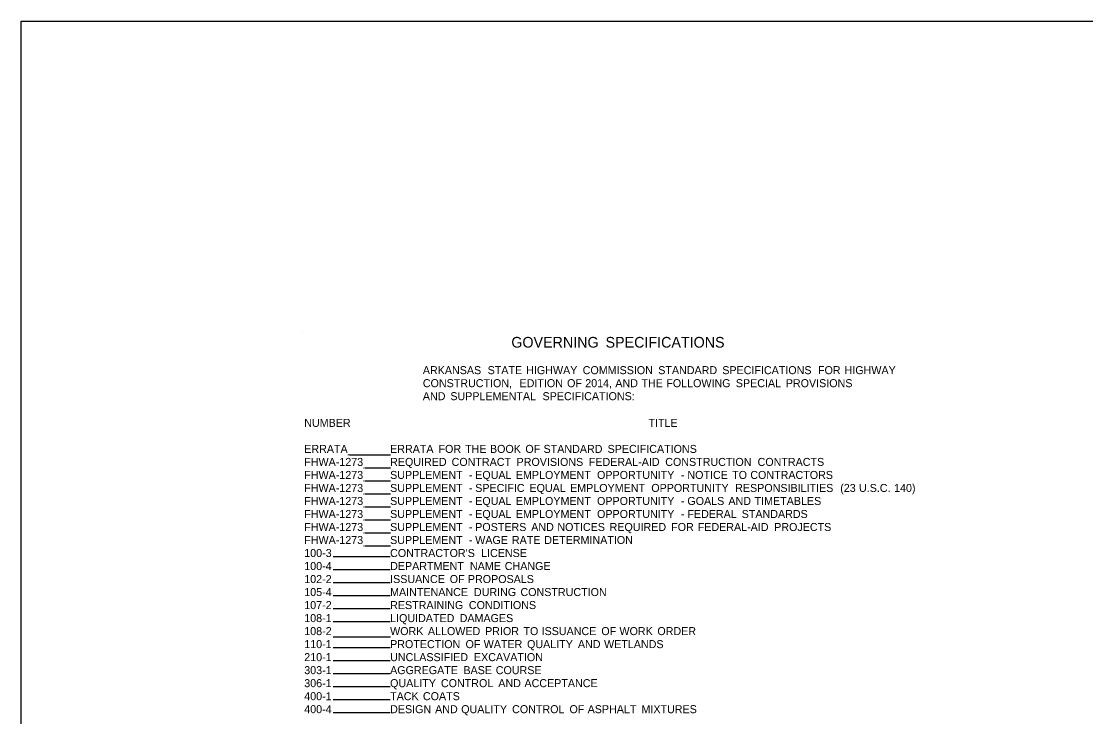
# Model space of a CAD drawing. Extents: x 1955683 to 1956002, y 566394 to 566602.
# Drawn here: x 1955683.4 to 1955842.9, y 566497.8 to 566602 of the extents above; entities that cross this region are included whole.
import ezdxf

# ---------------------------------------------------------------- set-up
doc = ezdxf.new("R2010")
doc.units = 0
for name, color, linetype in [('Default', 7, 'Continuous'), ('R_Border', 7, 'Continuous'), ('R_Border Prem', 7, 'Continuous')]:
    doc.layers.add(name, color=color, linetype=linetype)

msp = doc.modelspace()

# ---------------------------------------------------------------- linework, layer by layer
at = {"layer": 'R_Border'}
for p, q in [((1955725.6, 566555.39), (1955725.6, 566555.39)), ((1955732.57, 566537.03), (1955738.72, 566537.03)), ((1955734.9, 566535.08), (1955738.72, 566535.08)), ((1955734.9, 566533.13), (1955738.72, 566533.13)), ((1955734.9, 566531.18), (1955738.72, 566531.18)), ((1955734.9, 566529.23), (1955738.72, 566529.23)), ((1955734.9, 566527.28), (1955738.72, 566527.28)), ((1955734.9, 566525.33), (1955738.72, 566525.33)), ((1955734.9, 566523.38), (1955738.72, 566523.38)), ((1955730.1, 566521.79), (1955738.66, 566521.79)), ((1955730.1, 566519.84), (1955738.66, 566519.84)), ((1955730.1, 566517.89), (1955738.66, 566517.89)), ((1955730.1, 566515.94), (1955738.66, 566515.94)), ((1955730.1, 566513.99), (1955738.66, 566513.99)), ((1955730.1, 566512.04), (1955738.66, 566512.04)), ((1955730.1, 566509.73), (1955738.72, 566509.73)), ((1955730.1, 566508.14), (1955738.66, 566508.14)), ((1955730.1, 566506.19), (1955738.66, 566506.19)), ((1955730.1, 566504.24), (1955738.66, 566504.24)), ((1955730.1, 566502.29), (1955738.66, 566502.29)), ((1955730.1, 566500.34), (1955738.66, 566500.34)), ((1955730.1, 566498.39), (1955738.66, 566498.39))]:
    msp.add_line(p, q, dxfattribs=at)
at = {"layer": 'R_Border Prem'}
msp.add_lwpolyline([(1956002.45, 566561.79), (1956002.45, 566393.51), (1955683.38, 566393.51), (1955683.38, 566601.97), (1955920.19, 566601.97), (1955920.19, 566592.09), (1955955.71, 566592.09), (1955955.71, 566588.52), (1955959.35, 566588.52), (1955959.35, 566589.17), (1955974.89, 566589.17)], dxfattribs=at)

# ---------------------------------------------------------------- texts
at = {"layer": 'Default'}
for s, height, p in [('GOVERNING', 1.6, (1955756.83, 566553.08)), (' SPECIFICATIONS', 1.6, (1955770.36, 566553.08)), ('           ARKANSAS', 1.2, (1955738.66, 566549.1)), (' STATE', 1.2, (1955752.83, 566549.1)), (' HIGHWAY', 1.2, (1955758.61, 566549.1)), (' COMMISSION', 1.2, (1955767.08, 566549.1)), (' STANDARD', 1.2, (1955778.4, 566549.1)), (' SPECIFICATIONS', 1.2, (1955788, 566549.1)), (' FOR', 1.2, (1955802.35, 566549.1)), (' HIGHWAY', 1.2, (1955806.33, 566549.1)), ('           CONSTRUCTION,', 1.2, (1955738.66, 566547.15)), (' EDITION', 1.2, (1955757.61, 566547.15)), (' OF', 1.2, (1955764.74, 566547.15)), (' 2014,', 1.2, (1955767.46, 566547.15)), (' AND', 1.2, (1955771.97, 566547.15)), (' THE', 1.2, (1955775.88, 566547.15)), (' FOLLOWING', 1.2, (1955779.61, 566547.15)), (' SPECIAL', 1.2, (1955790.03, 566547.15)), (' PROVISIONS', 1.2, (1955797.52, 566547.15)), ('           AND', 1.2, (1955738.66, 566545.2)), (' SUPPLEMENTAL', 1.2, (1955747.24, 566545.2)), (' SPECIFICATIONS:', 1.2, (1955761.06, 566545.2)), ('NUMBER', 1.2, (1955725.79, 566541.2)), ('TITLE', 1.2, (1955777.38, 566541.2)), ('ERRATA______', 1.2, (1955725.79, 566537.3)), ('ERRATA', 1.2, (1955738.66, 566537.3)), (' FOR', 1.2, (1955745.47, 566537.3)), (' THE', 1.2, (1955749.45, 566537.3)), (' BOOK', 1.2, (1955753.18, 566537.3)), (' OF', 1.2, (1955758.49, 566537.3)), (' STANDARD', 1.2, (1955761.21, 566537.3)), (' SPECIFICATIONS', 1.2, (1955770.81, 566537.3)), ('FHWA-1273___', 1.2, (1955725.79, 566535.35)), ('REQUIRED', 1.2, (1955738.66, 566535.35)), (' CONTRACT', 1.2, (1955747.43, 566535.35)), (' PROVISIONS', 1.2, (1955757.17, 566535.35)), (' FEDERAL-AID', 1.2, (1955767.99, 566535.35)), (' CONSTRUCTION', 1.2, (1955779.45, 566535.35)), (' CONTRACTS', 1.2, (1955793.29, 566535.35)), ('FHWA-1273___', 1.2, (1955725.79, 566533.4)), ('SUPPLEMENT', 1.2, (1955738.66, 566533.4)), (' -', 1.2, (1955750, 566533.4)), (' EQUAL', 1.2, (1955750.97, 566533.4)), (' EMPLOYMENT', 1.2, (1955757.06, 566533.4)), (' OPPORTUNITY', 1.2, (1955769.23, 566533.4)), (' -', 1.2, (1955781.8, 566533.4)), (' NOTICE', 1.2, (1955782.77, 566533.4)), (' TO', 1.2, (1955789.48, 566533.4)), (' CONTRACTORS', 1.2, (1955792.2, 566533.4)), ('FHWA-1273___', 1.2, (1955725.79, 566531.45)), ('SUPPLEMENT', 1.2, (1955738.66, 566531.45)), (' -', 1.2, (1955750, 566531.45)), (' SPECIFIC', 1.2, (1955750.97, 566531.45)), (' EQUAL', 1.2, (1955759.1, 566531.45)), (' EMPLOYMENT', 1.2, (1955765.19, 566531.45)), (' OPPORTUNITY', 1.2, (1955777.36, 566531.45)), (' RESPONSIBILITIES', 1.2, (1955789.93, 566531.45)), (' (23', 1.2, (1955805.68, 566531.45)), (' U.S.C.', 1.2, (1955808.49, 566531.45)), (' 140)', 1.2, (1955813.75, 566531.45)), ('FHWA-1273___', 1.2, (1955725.79, 566529.5)), ('SUPPLEMENT', 1.2, (1955738.66, 566529.5)), (' EQUAL', 1.2, (1955750.97, 566529.5)), (' EMPLOYMENT', 1.2, (1955757.06, 566529.5)), (' OPPORTUNITY', 1.2, (1955769.23, 566529.5)), (' GOALS', 1.2, (1955782.77, 566529.5)), (' AND', 1.2, (1955788.92, 566529.5)), (' TIMETABLES', 1.2, (1955792.84, 566529.5)), ('FHWA-1273___', 1.2, (1955725.79, 566527.55)), ('SUPPLEMENT', 1.2, (1955738.66, 566527.55)), (' -', 1.2, (1955750, 566529.5)), (' EQUAL', 1.2, (1955750.97, 566527.55)), (' EMPLOYMENT', 1.2, (1955757.06, 566527.55)), (' OPPORTUNITY', 1.2, (1955769.23, 566527.55)), (' -', 1.2, (1955781.8, 566529.5)), (' FEDERAL', 1.2, (1955782.77, 566527.55)), (' STANDARDS', 1.2, (1955790.91, 566527.55)), (' -', 1.2, (1955750, 566527.55)), (' -', 1.2, (1955781.8, 566527.55)), ('FHWA-1273___', 1.2, (1955725.79, 566525.6)), ('SUPPLEMENT', 1.2, (1955738.66, 566525.6)), (' -', 1.2, (1955750, 566525.6)), (' POSTERS', 1.2, (1955750.97, 566525.6)), (' AND', 1.2, (1955759.36, 566525.6)), (' NOTICES', 1.2, (1955763.28, 566525.6)), (' REQUIRED', 1.2, (1955771.11, 566525.6)), (' FOR', 1.2, (1955780.34, 566525.6)), (' FEDERAL-AID', 1.2, (1955784.32, 566525.6)), (' PROJECTS', 1.2, (1955795.78, 566525.6)), ('FHWA-1273___', 1.2, (1955725.79, 566523.65)), ('SUPPLEMENT', 1.2, (1955738.66, 566523.65)), (' -', 1.2, (1955750, 566523.65)), (' WAGE', 1.2, (1955750.97, 566523.65)), (' RATE', 1.2, (1955756.47, 566523.65)), (' DETERMINATION', 1.2, (1955761.32, 566523.65)), ('100-3', 1.2, (1955725.79, 566521.7)), ("CONTRACTOR'S", 1.2, (1955738.66, 566521.7)), (' LICENSE', 1.2, (1955751.85, 566521.7)), ('100-4', 1.2, (1955725.79, 566519.75)), ('DEPARTMENT', 1.2, (1955738.66, 566519.75)), (' NAME', 1.2, (1955750.18, 566519.75)), (' CHANGE', 1.2, (1955755.4, 566519.75)), ('102-2', 1.2, (1955725.79, 566517.8)), ('ISSUANCE', 1.2, (1955738.66, 566517.8)), (' OF', 1.2, (1955747.15, 566517.8)), (' PROPOSALS', 1.2, (1955749.87, 566517.8)), ('105-4', 1.2, (1955725.79, 566515.85)), ('MAINTENANCE', 1.2, (1955738.66, 566515.85)), (' DURING', 1.2, (1955750.78, 566515.85)), (' CONSTRUCTION', 1.2, (1955757.75, 566515.85)), ('107-2', 1.2, (1955725.79, 566513.9)), ('RESTRAINING', 1.2, (1955738.66, 566513.9)), (' CONDITIONS', 1.2, (1955750.02, 566513.9)), ('108-1', 1.2, (1955725.79, 566511.95)), ('LIQUIDATED', 1.2, (1955738.66, 566511.95)), (' DAMAGES', 1.2, (1955748.64, 566511.95)), ('108-2', 1.2, (1955725.79, 566510)), ('WORK', 1.2, (1955738.66, 566510)), (' ALLOWED', 1.2, (1955743.88, 566510)), (' PRIOR', 1.2, (1955752.45, 566510)), (' TO', 1.2, (1955758.2, 566510)), (' ISSUANCE', 1.2, (1955760.92, 566510)), (' OF', 1.2, (1955769.87, 566510)), (' WORK', 1.2, (1955772.59, 566510)), (' ORDER', 1.2, (1955778.27, 566510)), ('110-1', 1.2, (1955725.79, 566508.05)), ('PROTECTION', 1.2, (1955738.66, 566508.05)), (' OF', 1.2, (1955749.52, 566508.05)), (' WATER', 1.2, (1955752.24, 566508.05)), (' QUALITY', 1.2, (1955758.74, 566508.05)), (' AND', 1.2, (1955766.36, 566508.05)), (' WETLANDS', 1.2, (1955770.28, 566508.05)), ('210-1', 1.2, (1955725.79, 566506.1)), ('UNCLASSIFIED', 1.2, (1955738.66, 566506.1)), (' EXCAVATION', 1.2, (1955750.78, 566506.1)), ('303-1', 1.2, (1955725.79, 566504.15)), ('AGGREGATE', 1.2, (1955738.66, 566504.15)), (' BASE', 1.2, (1955749.2, 566504.15)), (' COURSE', 1.2, (1955754.05, 566504.15)), ('306-1', 1.2, (1955725.79, 566502.2)), ('QUALITY', 1.2, (1955738.66, 566502.2)), (' CONTROL', 1.2, (1955745.83, 566502.2)), (' AND', 1.2, (1955754.43, 566502.2)), (' ACCEPTANCE', 1.2, (1955758.35, 566502.2)), ('400-1', 1.2, (1955725.79, 566500.25)), ('TACK', 1.2, (1955738.66, 566500.25)), (' COATS', 1.2, (1955743.13, 566500.25)), ('400-4', 1.2, (1955725.79, 566498.3)), ('DESIGN', 1.2, (1955738.66, 566498.3)), (' AND', 1.2, (1955744.96, 566498.3)), (' QUALITY', 1.2, (1955748.87, 566498.3)), (' CONTROL', 1.2, (1955756.5, 566498.3)), (' OF', 1.2, (1955765.1, 566498.3)), (' ASPHALT', 1.2, (1955767.82, 566498.3)), (' MIXTURES', 1.2, (1955775.89, 566498.3))]:
    msp.add_text(s, height=height, dxfattribs=at).set_placement(p)

doc.saveas('drawing.dxf')
